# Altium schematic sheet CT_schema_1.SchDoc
size 455 x 258 mm
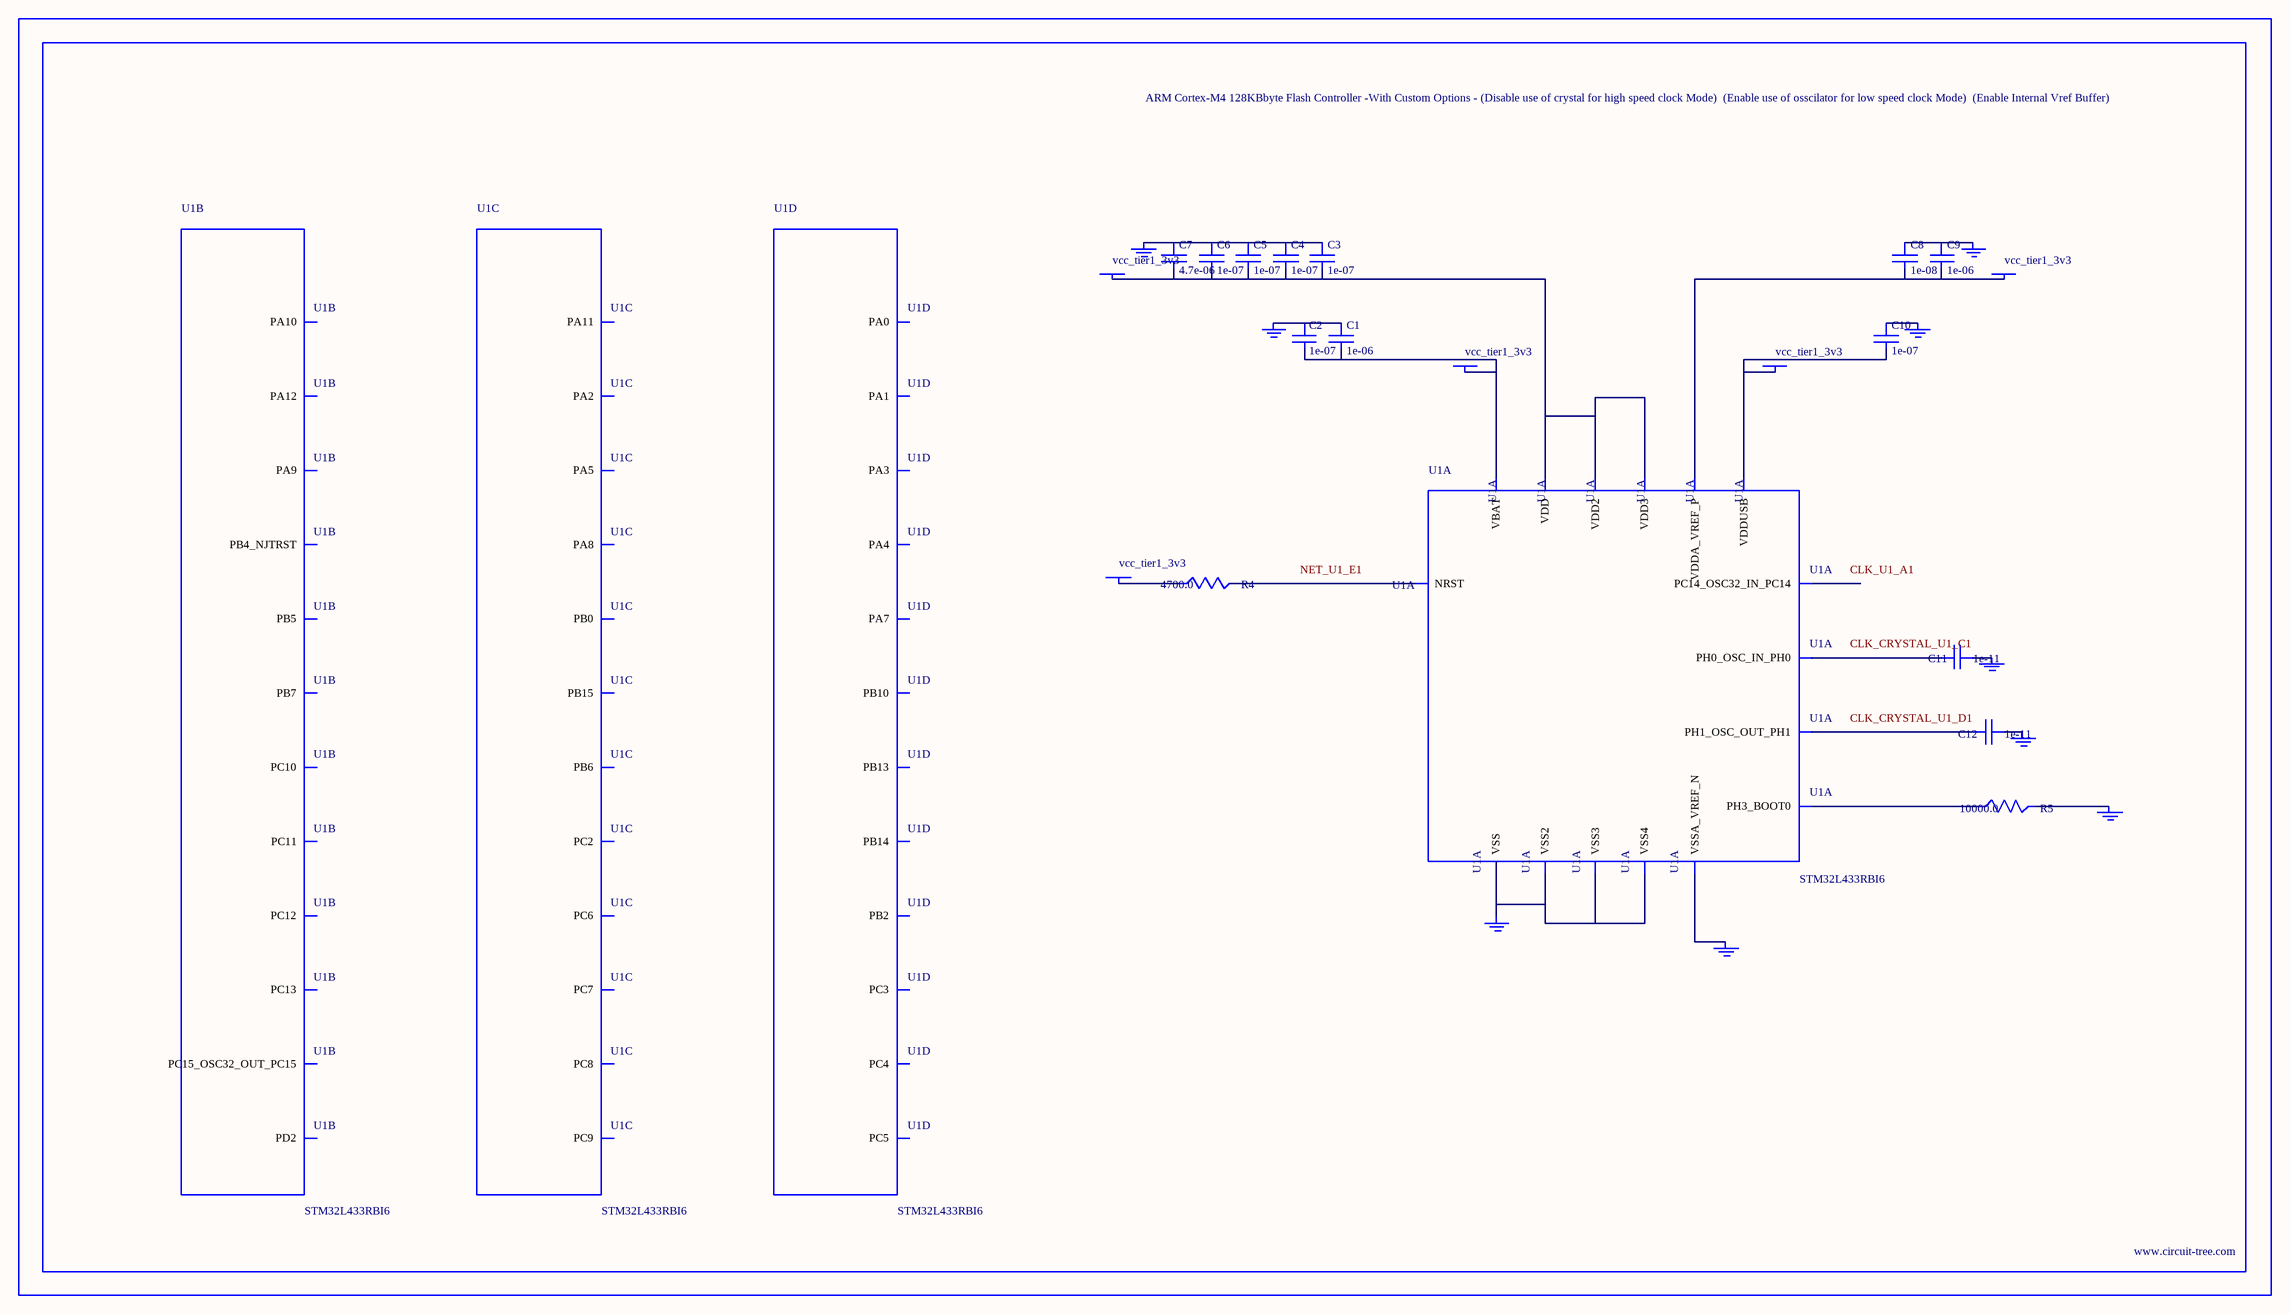
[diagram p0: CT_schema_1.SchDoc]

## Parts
BORDER0  (no value)
C1  1e-06  [C0603]
C2  1e-07  [C0603]
C3  1e-07  [C0603]
C4  1e-07  [C0603]
C5  1e-07  [C0603]
C6  1e-07  [C0603]
C7  4.7e-06  [C0603]
C8  1e-08  [C0603]
C9  1e-06  [C0603]
C10  1e-07  [C0603]
C11  1e-11  [C0402]
C12  1e-11  [C0402]
GND_INSTANCE_0_0  (no value)
GND_INSTANCE_0_1  (no value)
GND_INSTANCE_0_2  (no value)
GND_INSTANCE_0_3  (no value)
GND_INSTANCE_0_4  (no value)
GND_INSTANCE_0_5  (no value)
GND_INSTANCE_0_6  (no value)
GND_INSTANCE_0_7  (no value)
GND_INSTANCE_0_8  (no value)
POWER_INSTANCE_0_0  vcc_tier1_3v3
POWER_INSTANCE_0_1  vcc_tier1_3v3
POWER_INSTANCE_0_2  vcc_tier1_3v3
POWER_INSTANCE_0_3  vcc_tier1_3v3
POWER_INSTANCE_0_4  vcc_tier1_3v3
R4  4700.0  [R0603]
R5  10000.0  [R0603]
U1  STM32L433RBI6  [UFBGA64]  (parts A,B,C,D of 7)

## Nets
NetC1_1: C1.1 C2.1 GND_INSTANCE_0_0.0(GND)
NetC1_2: C1.2 C2.2 POWER_INSTANCE_0_0.0(PWR) U1.B2(VBAT)
NetC3_1: C3.1 C4.1 C5.1 C6.1 C7.1 GND_INSTANCE_0_1.0(GND)
NetC3_2: C3.2 C4.2 C5.2 C6.2 C7.2 POWER_INSTANCE_0_1.0(PWR) U1.D2(VDD) U1.E4(VDD2) U1.E6(VDD3)
NetC8_1: C8.1 C9.1 GND_INSTANCE_0_3.0(GND)
NetC8_2: C8.2 C9.2 POWER_INSTANCE_0_2.0(PWR) U1.H1(VDDA_VREF_P)
NetC10_1: C10.1 GND_INSTANCE_0_4.0(GND)
NetC10_2: C10.2 POWER_INSTANCE_0_3.0(PWR) U1.E5(VDDUSB)
NetC11_1: C11.1 GND_INSTANCE_0_5.0(GND)
NetC11_2: C11.2 U1.C1(PH0_OSC_IN_PH0)
NetC12_1: C12.1 GND_INSTANCE_0_6.0(GND)
NetC12_2: C12.2 U1.D1(PH1_OSC_OUT_PH1)
NetGND_INSTANCE_0_2_0: GND_INSTANCE_0_2.0(GND) R5.2
NetGND_INSTANCE_0_7_0: GND_INSTANCE_0_7.0(GND) U1.F1(VSSA_VREF_N)
NetGND_INSTANCE_0_8_0: GND_INSTANCE_0_8.0(GND) U1.C2(VSS) U1.D4(VSS2) U1.D5(VSS3) U1.D6(VSS4)
NetPOWER_INSTANCE_0_4_0: POWER_INSTANCE_0_4.0(PWR) R4.1
NetR4_2: R4.2 U1.E1(NRST)
NetR5_1: R5.1 U1.B4(PH3_BOOT0)

Not connected (* = marked no-connect by the designer): U1 A1(PC14_OSC32_IN_PC14) A2(PC13) A4(PB4_NJTRST) B1(PC15_OSC32_OUT_PC15) B5(PD2) B6(PC11) B7(PC10) B8(PA12) C3(PB7) C4(PB5) C5(PC12) C6(PA10) C7(PA9) C8(PA11) D3(PB6) D7(PA8) D8(PC9) E7(PC7) E8(PC8) F2(PC2) F3(PA2) F4(PA5) F5(PB0) F6(PC6) F7(PB15) F8(PB14) G1(PC3) G2(PA0) G3(PA3) G6(PB2) G7(PB10) G8(PB13) H2(PA1) H3(PA4) H4(PA7) H5(PC4) H6(PC5)

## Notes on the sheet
- Labels drawn without touching a wire or pin: CLK_CRYSTAL_U1_C1, CLK_CRYSTAL_U1_D1, CLK_U1_A1, NET_U1_E1

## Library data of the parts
BORDER0 = BORDER_PAGE0
C1 C9 = C0603C105K3RACTU
C2-C6 C10 = 06035C104K4Z2A
C7 = GRM188R6YA475KE15D
C8 = 06035C103K4Z2A
C11 C12 = C0402C100K3GACTU
GND_INSTANCE_0_0-GND_INSTANCE_0_8 = GND
POWER_INSTANCE_0_0-POWER_INSTANCE_0_4 = PWR
R4 = RC0603JR-074K7L
R5 = RC0603JR-0710KL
